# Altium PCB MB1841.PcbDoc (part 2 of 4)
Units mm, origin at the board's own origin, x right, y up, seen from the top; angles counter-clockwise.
Board outline 70 x 82.5 mm, 4 copper layers (Top Layer, Signal Layer 1, Signal Layer 2, Bottom Layer), stack 1.49 mm thick; 252 components, 169 nets, 1058 pads, 796 vias.
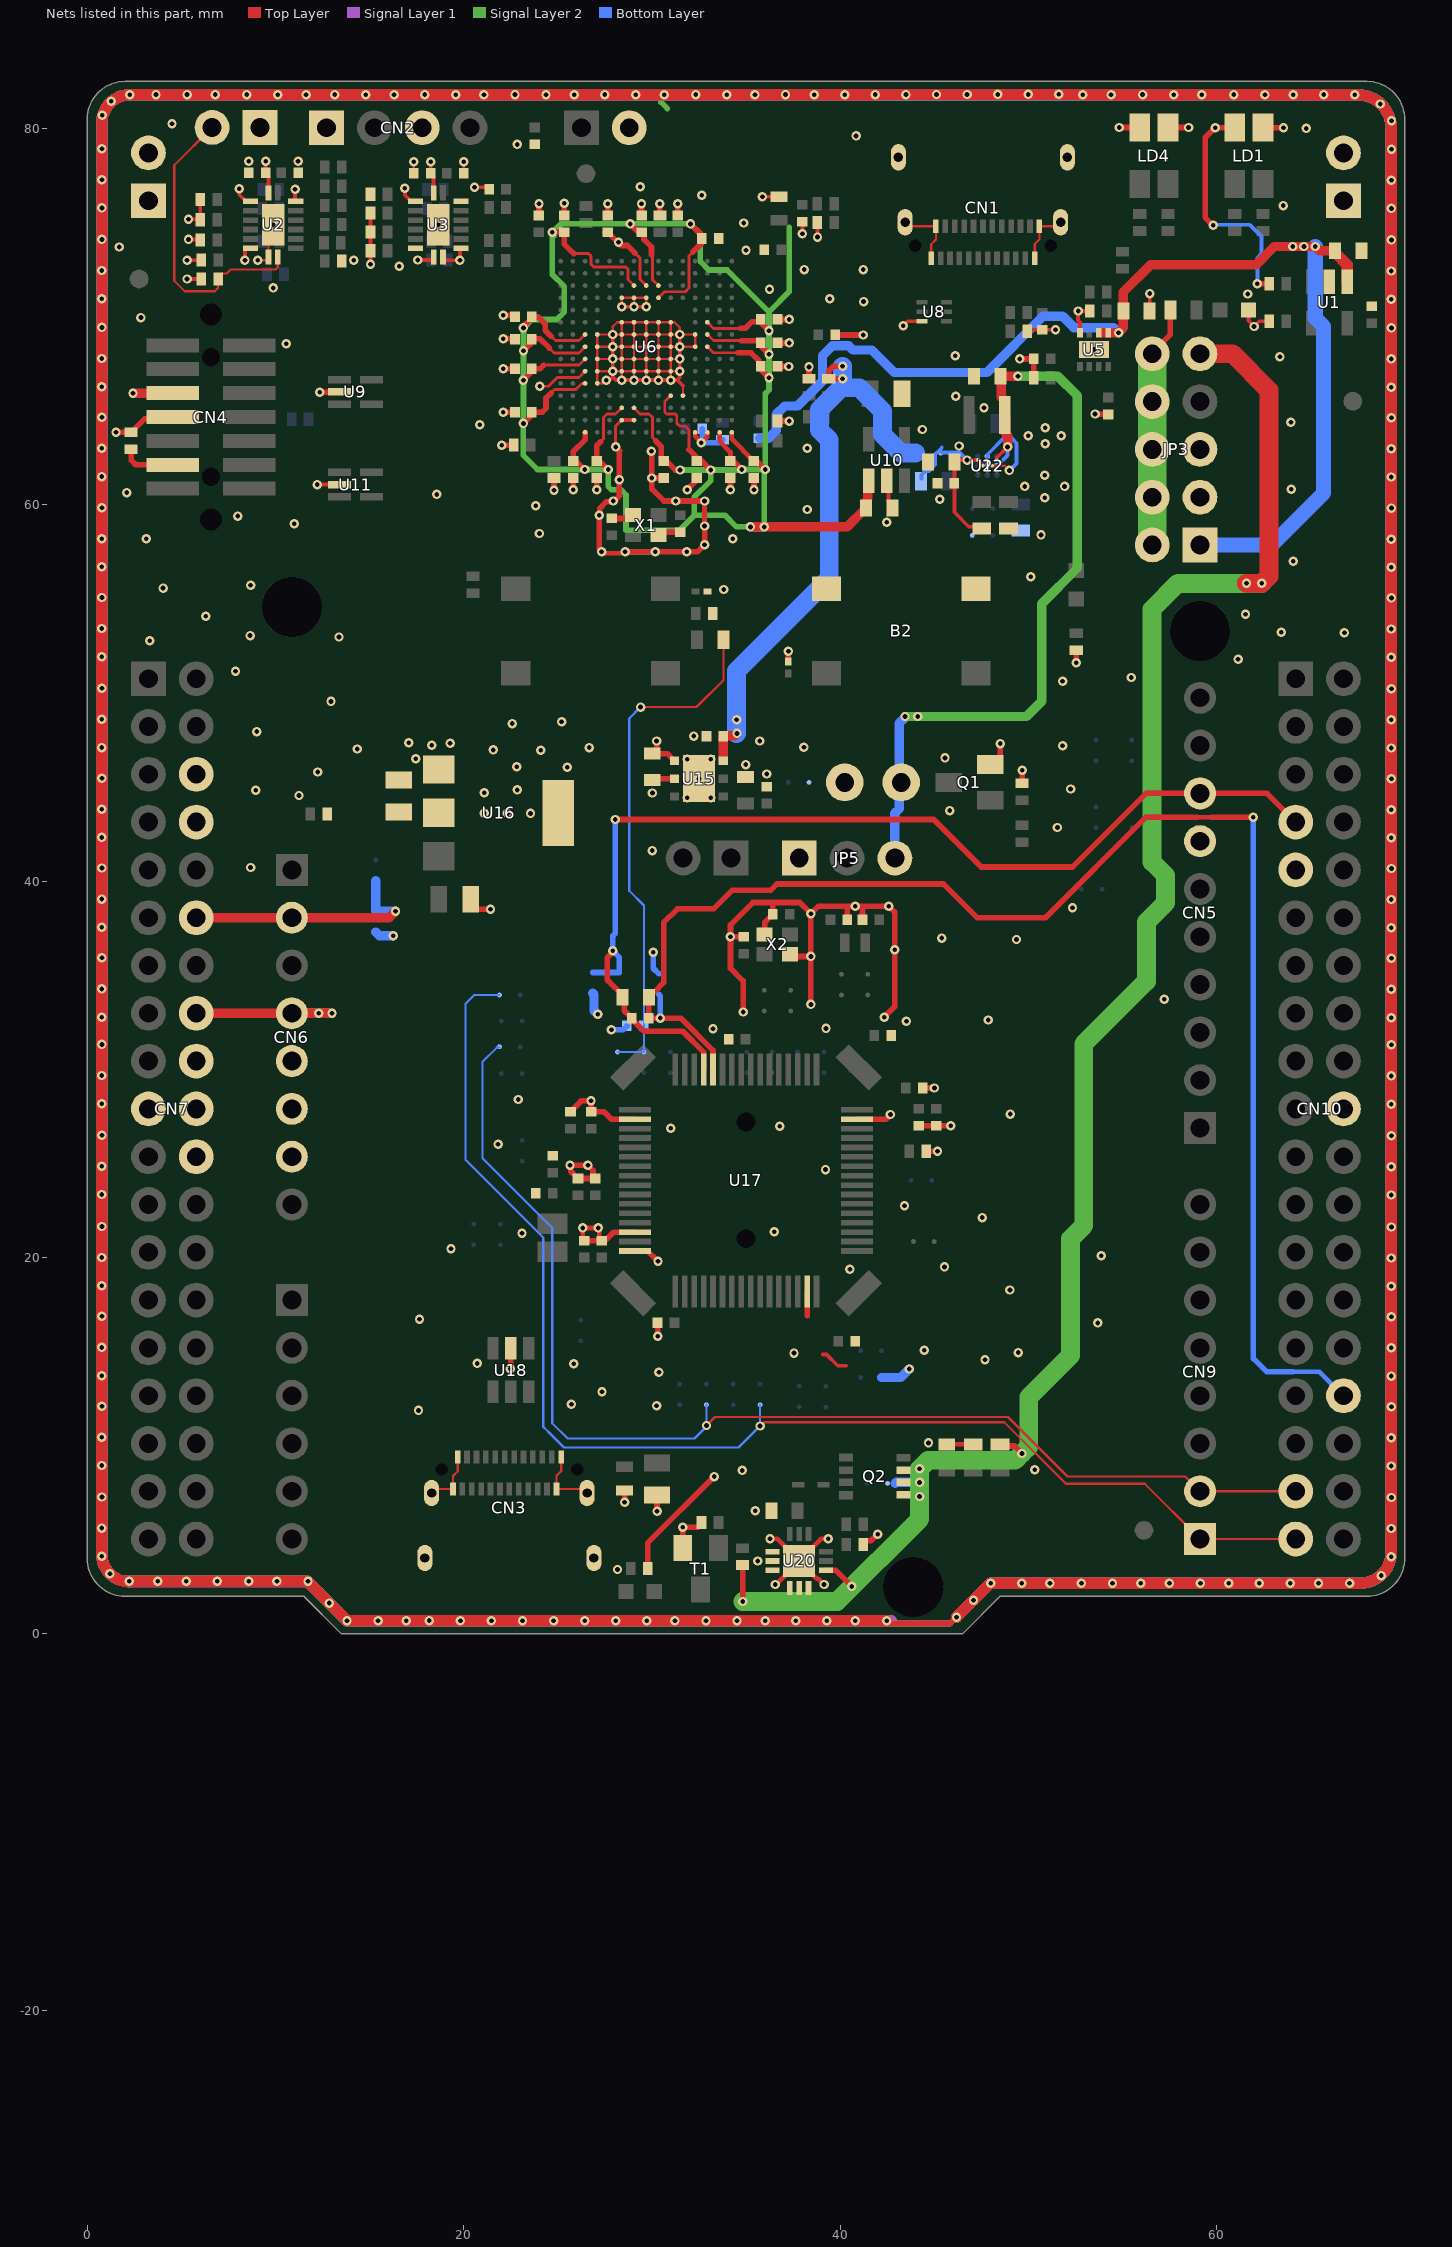
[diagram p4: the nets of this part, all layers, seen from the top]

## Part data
B1 B2: library part MCD-02524, "Push Button, SPST-NO, 0.05A, 12V SMT, T=7.30mm, changeable caps AKTSC62x", Manufacturer="APEM INC", Manufacturer_Part_Number=ADTSM644SVTR, Package=N/A
C1 C2 C3 C4 C5 C9 C10 C11 C13 C19 C20 C22 C23 C25 C26 C30 C32 C33 C34 C35 C36 C37 C38 C42 C46 C53 C54 C55 C56 C57 C60 C63 C66 C67 C68 C72: library part MCD-00006, "Capacitor, MLCC, 100nF, 16V, X7R, +/-10%, 0402, T=0.5mm", Manufacturer=YAGEO, Manufacturer_Part_Number=CC0402KRX7R7BB104, Package=0402
C6: library part MCD-00016, "Capacitor, MLCC, 20pF, 50V, NPO, +/- 5%, 0402, T=0.5mm", Manufacturer=YAGEO, Manufacturer_Part_Number=CC0402JRNPO9BN200, Package=0402
C7 C18 C24: library part MCD-02198, "Capacitor, MLCC, 10nF, 50V, X7R, +/-10%, 0402, T=0.5mm", Manufacturer=YAGEO, Manufacturer_Part_Number=CC0402KRX7R9BB103, Package=0402
C8 C12 C21: library part MCD-02606, "Capacitor, MLCC, 2.2uF, 6.3V, X5R, +/-10%, 0402, T=0.5mm", Manufacturer=YAGEO, Manufacturer_Part_Number=CC0402KRX5R5BB225, Package=0402
C14 C16 C39: library part MCD-00099, "Capacitor, MLCC, 10uF, 10V, X5R, +/-10%, 0603, T=0.8mm", Manufacturer=MURATA, Manufacturer_Part_Number=GRM188R61A106KE69D, Package=0603
C15 C64: library part MCD-00205, "Capacitor, MLCC, 100pF, 50V, NPO, +/-5%, 0402, T=0.5mm", Manufacturer=YAGEO, Manufacturer_Part_Number=CC0402JRNPO9BN101, Package=0402
C17 C29: library part MCD-02355, "Capacitor, MLCC, 100nF, 25V, X7R, +/-10%, 0402, T=0.5mm", Manufacturer=WALSIN, Manufacturer_Part_Number=0402B104K250CT, Package=0402
C27 C31: library part MCD-00243, "Capacitor, MLCC, 10uF, 6V3, X5R, +/-10%, 0603, T=0.8mm", Manufacturer=YAGEO, Manufacturer_Part_Number=CC0603KRX5R5BB106, Package=0603
C28 C70: library part MCD-02372, "Capacitor, MLCC, 2.2uF, 25V, X7R, +/-10%, 0805, T=1,25mm", Manufacturer=MURATA, Manufacturer_Part_Number=GRM21BR71E225KE11L, Package=0805
C40 C41: library part MCD-01374, "Capacitor, MLCC, 5.6pF, 50V, NPO, +/-0.1pF, 0402, T=0.5mm", Manufacturer=YAGEO, Manufacturer_Part_Number=CC0402BRNPO9BN5R6, Package=0402
C43 C44 C52: library part MCD-00010, "Capacitor, MLCC, 1uF, 16V, X5R, +/-10%, 0603, T=0.8mm", Manufacturer=YAGEO, Manufacturer_Part_Number=CC0603KRX5R7BB105, Package=0603
C45 C47: library part MCD-00014, "Capacitor, MLCC, 10uF, 25V, X5R, +/-10%, 0805, T=0.85mm", Manufacturer=YAGEO, Manufacturer_Part_Number=CC0805KRX5R8BB106, Package=0805
C48 C49 C50 C51: library part MCD-00674, "Capacitor, MLCC, 6.8pF, 50V, NPO, +/-0.25pF, 0402, T=0.5mm", Manufacturer=YAGEO, Manufacturer_Part_Number=CC0402CRNPO9BN6R8, Package=0402
C58 C65: library part MCD-01823, "Capacitor, MLCC, 2.2uF, 6V3, X5R,+/-10%, 0402, T=0.5mm", Manufacturer=MURATA, Manufacturer_Part_Number=GRM155R60J225KE95D, Package=0402
C59 C61 C62: library part MCD-01355, "Capacitor, MLCC, 10uF, 4V, X5R, +/-20%, 0402, T=0.5mm", Manufacturer=MURATA, Manufacturer_Part_Number=GRM155R60G106ME44, Package=0402
C69: library part MCD-00637, "Capacitor, MLCC, 10pF, 50V, NPO, +/-5%, 0603, T=0.8mm", Manufacturer=YAGEO, Manufacturer_Part_Number=CC0603JRNPO9BN100, Package=0603
C71: library part MCD-01099, "Capacitor, MLCC, 100nF, 50V, X7R, +/-10%, 0603, T=0.8mm", Manufacturer=YAGEO, Manufacturer_Part_Number=CC0603KRX7R9BB104, Package=0603
C73: library part MCD-00011, "Capacitor, MLCC, 10nF, 16V, X7R, +/-10%, 0402, T=0.5mm", Manufacturer=YAGEO, Manufacturer_Part_Number=CC0402KRX7R7BB103, Package=0402
CN1 CN3: library part MCD-03232, "USB_TypeC, 24 pins, RA, SMD, T=2.96mm (USB Certified 3.1)", Manufacturer="AMPHENOL ICC", Manufacturer_Part_Number=12401826E412A
CN2: library part MCD-00029, "Header, 4x1, 2.54mm, VR, TH, T=5.84mm/2.54mm", Manufacturer=SAMTEC, Manufacturer_Part_Number=TSW-104-07-G-S
CN4: library part MCD-01226, "Header, 5x2, 1.27mm, VR, SMD, T=5.97mm/3.05mm", Manufacturer=SAMTEC, Manufacturer_Part_Number=FTSH-105-01-L-DV-K
CN5: library part MCD-02625, "Socket, 10x1, 2.54mm, VR, TH, T=8.51mm/10mm", Manufacturer=SAMTEC, Manufacturer_Part_Number=SSQ-110-03-F-S
CN6 CN9: library part MCD-02624, "Socket, 8x1, 2.54mm, VR, TH, T=8.51mm/10mm", Manufacturer=SAMTEC, Manufacturer_Part_Number=SSQ-108-03-F-S
CN7 CN10: library part MCD-00213, "Header, 19x2, 2.54mm, VR, TH, T=5.84mm/10.16mm", Manufacturer=SAMTEC, Manufacturer_Part_Number=TSW-119-09-G-D
CN8: library part MCD-02623, "Socket, 6x1, 2.54mm, VR, TH, T=8.51mm/10mm", Manufacturer=SAMTEC, Manufacturer_Part_Number=SSQ-106-03-F-S
CN11 CN12: library part MCD-00214, "Header, 2x1, 2.54mm, VR, TH, T=5.84mm/10.16mm", Manufacturer=SAMTEC, Manufacturer_Part_Number=TSW-102-09-G-S
D1: library part MCD-01677, "Small signal Schottky diodes", Manufacturer=STMICROELECTRONICS, Manufacturer_HQ_COO=EU, Manufacturer_Part_Number=BAT54KFILM, Package=SOD-523
HW1: library part MCD-00547, "Sticker product 25x9 mm", Manufacturer=N/A
JP1 JP2: library part MCD-00045, "Header, 2x1, 2.54mm, VR, TH, T=5.84mm/2.54mm", Manufacturer=SAMTEC, Manufacturer_Part_Number=TSW-102-07-G-S
JP3: library part MCD-01203, "Header, 5x2, 2.54mm, VR, TH, T=5.84mm/2.54mm", Manufacturer=SAMTEC, Manufacturer_Part_Number=TSW-105-07-G-D
JP4: library part MCD-00683, "Header, 2x1, 2.54mm, VR, TH, T=5.84mm/2.54mm", Manufacturer=SAMTEC, Manufacturer_Part_Number=TSW-102-07-G-S
JP5: library part MCD-00684, "Header, 3x1, 2.54mm, VR, TH, T=5.84mm/2.54mm", Manufacturer=SAMTEC, Manufacturer_Part_Number=TSW-103-07-F-S
L1: library part MCD-00240, "Inductor, 2.2uH, +/-20%, 2.6A, 100mR, 2.5x2mm, T=1mm", Manufacturer=TDK, Manufacturer_Part_Number=VLS252010HBX-2R2M-1, Package=2.5x2mm
L2: library part MCD-01060, "Inductor, 2.2uH, +/-20%, 0.7A, 0R156, 0805, T=0.9mm", Manufacturer=MURATA, Manufacturer_Part_Number=LQM21PN2R2MGH, Package=0805
LD1 LD4: library part MCD-02631, "LED Bicolor, Green/Red, 2V, 20mA,  4-PLCC", Manufacturer="WURTH ELEKTRONIK", Manufacturer_Part_Number=150141SV73110, Package=4-PLCC
LD2 LD3 LD6: library part MCD-00588, "LED Green, 0603 SMD, Forward Voltage Typ=2V, Max=2.5V", Manufacturer="OSRAM OPTO SEMICONDUCTORS", Manufacturer_Part_Number="LG Q396-PS-35", Package="LED 0603"
Q1 T1: library part MCD-00073, "NPN Bipolar Transistor", Manufacturer="ON SEMICONDUCTOR", Manufacturer_Part_Number=BSR14, Package=SOT23
Q2: library part MCD-01810, "N-channel 30 V, 6 mΩ typ, 11 A STripFET™ H6, Power MOSFET in a PowerFLAT™ 3.3x3.3 package", Manufacturer=STMICROELECTRONICS, Manufacturer_HQ_COO=EU, Package="PowerFLAT 3.3x3.3"
R1 R2 R6 R21: library part MCD-00481, "Resistor, 47R, 0402, +/-1%, 1/16W", Manufacturer=YAGEO, Manufacturer_Part_Number=RC0402FR-0747RL, Package=0402
R3 R4 R5 R9 R15 R17 R18 R19 R20 R22 R24 R25 R26 R28 R29 R34 R35 R37 R48 R51: library part MCD-00059, "Resistor, 100K, 0402, +/-1%, 1/16W", Manufacturer=YAGEO, Manufacturer_Part_Number=RC0402FR-07100KL, Package=0402
R7 R42: library part MCD-00067, "Resistor, 100R, 0402, +/- 1%, 1/16W", Manufacturer=YAGEO, Manufacturer_Part_Number=RC0402FR-07100RL, Package=0402
R8 R40 R47 R66 R102 R103 R104 R105 R106 R107 R108 R109: library part MCD-00052, "Resistor, 0R, 0402, +/-5%, 1/16W", Manufacturer=YAGEO, Manufacturer_Part_Number=RC0402JR-070RL, Package=0402
R10 R12: library part MCD-00062, "Resistor, 330R, 0402, +/-1%, 1/16W", Manufacturer=YAGEO, Manufacturer_Part_Number=RC0402FR-07330RL, Package=0402
R11 R13: library part MCD-02665, "Resistor, 1K, 0402, +/-0.1%, 1/16W, +/-25ppm/°C", Manufacturer=YAGEO, Manufacturer_Part_Number=RT0402BRD071KL, Package=0402
R14 R27: library part MCD-00185, "Resistor, 3K, 0402, +/-1%, 1/16W", Manufacturer=YAGEO, Manufacturer_Part_Number=RC0402FR-073KL, Package=0402
R16 R36 R39: library part MCD-00333, "Resistor, 5K1, 0402, +/-1%, 1/16W", Manufacturer=YAGEO, Manufacturer_Part_Number=RC0402FR-075K1L, Package=0402
R23: library part MCD-00409, "Resistor, 1K8, 0402, +/-1%, 1/16W", Manufacturer=YAGEO, Manufacturer_Part_Number=RC0402FR-071K8L, Package=0402
R30: library part MCD-00381, "Resistor, 1K3, 0402, +/-1%, 1/16W", Manufacturer=YAGEO, Manufacturer_Part_Number=RC0402FR-071K3L, Package=0402
R31 R33: library part MCD-02455, "Resistor, 3K9, 0402, +/-1%, 1/16W, +/-100ppm/°C", Manufacturer=YAGEO, Manufacturer_Part_Number=RC0402FR-073K9L, Package=0402
R32: library part MCD-00225, "Resistor, 510R, 0603, +/-1%, 1/10W", Manufacturer=YAGEO, Manufacturer_Part_Number=RC0603FR-07510RL, Package=0603
R38 R41 R43 R44 R54 R57 R58 R65: library part MCD-00053, "Resistor, 10K, 0402, +/-1%, 1/16W", Manufacturer=YAGEO, Manufacturer_Part_Number=RC0402FR-0710KL, Package=0402
R45 R46 R50 R62 R63: library part MCD-00056, "Resistor, 0R, 0603, +/-5%, 1/10W", Manufacturer=YAGEO, Manufacturer_Part_Number=RC0603JR-070RL, Package=0603
R49 R61: library part MCD-00441, "Resistor, 270R, 0402, +/-1%, 1/16W", Manufacturer=YAGEO, Manufacturer_Part_Number=RC0402FR-07270RL, Package=0402
R52: library part MCD-00061, "Resistor, 1K, 0402, +/-1%,1/16W", Manufacturer=YAGEO, Manufacturer_Part_Number=RC0402FR-071KL, Package=0402
R53 R60: library part MCD-00063, "Resistor, 47K, 0402, +/-1%, 1/16W", Manufacturer=YAGEO, Manufacturer_Part_Number=RC0402FR-0747KL, Package=0402
R55: library part MCD-01171, "Resistor, 49K9, 0603, +/-1%, 1/10W", Manufacturer=YAGEO, Manufacturer_Part_Number=RC0603FR-0749K9L, Package=0603
R56: library part MCD-00458, "Resistor, 330K, 0603, +/-1%, 1/10W", Manufacturer=YAGEO, Manufacturer_Part_Number=RC0603FR-07330KL, Package=0603
R59: library part MCD-00433, "Resistor, 2K4, 0402, +/-1%, 1/16W", Manufacturer=YAGEO, Manufacturer_Part_Number=RC0402FR-072K4L, Package=0402
R64: library part MCD-00242, "Resistor, 19K6, 0603, +/-1%, 1/10W", Manufacturer=YAGEO, Manufacturer_Part_Number=RC0603FR-0719K6L, Package=0603
SB1 SB2 SB3 SB4 SB5 SB6 SB7 SB8 SB9 SB10 SB11 SB12 SB13 SB14 SB15 SB16 SB17 SB18 SB19 SB20 SB21 SB22 SB23 SB24 SB25 SB26 SB27 SB28 SB29 SB30 SB31 SB32 SB33 SB34 SB35 SB36 SB37 SB38 SB39 SB40 SB41 SB42 SB43 SB44 SB45: library part MCD-00071, "Solder Bridge ON", Manufacturer=YAGEO, Manufacturer_Part_Number=RC0603JR-070RL, Package=SB0603
TP1: library part MCD-00074, "Test Point 1mm", Manufacturer=N/A
TP2 TP3: library part MCD-01506, "Test Point trought hole 1mm/2mm", Manufacturer=N/A
U1: library part MCD-00159, "IC, Enhanced single channel power switches", Manufacturer=STMICROELECTRONICS, Package=SOT23-5
U2 U3: library part MCD-01945, "4-bit dual supply translating transceiver with configurable voltage translation; 3-state", Manufacturer=NEXPERIA, Manufacturer_Part_Number=74AVC4TD245BQ,115, Package=DHVQFN16
U4 U19: library part MCD-01207, "High power Transient voltage suppressor:25V/35A EOS and ESD transients protection.", Manufacturer=STMICROELECTRONICS, Manufacturer_HQ_COO=EU, Manufacturer_Part_Number=ESDA25P35-1U1M, Package=QFN1610
U5: library part MCD-02532, "IC, eFuse with Fast Overvoltage Protection 2.7V to 18V 4A 34mOhm 8-Pin WSON", Manufacturer="TEXAS INSTRUMENTS", Package=WSON8
U6: library part MCD-03851, "MCU, ARM Cortex-M7 32-bit, 512KB Flash, 276KB RAM, With Crypto", Manufacturer=STMICROELECTRONICS, Manufacturer_Part_Number=STM32F723IEK6, Package=BGA-176
U8: library part MCD-00649, "Common mode filter with ESD protection for USB 2.0 interface", Manufacturer=STMICROELECTRONICS, Manufacturer_HQ_COO=EU
U9 U11: library part MCD-00136, "Dual Transil array for ESD protection", Manufacturer=STMICROELECTRONICS, Manufacturer_HQ_COO=EU
U10: library part MCD-02514, "LDO, 3.3V, 300mA, High input voltage: 2.5V to 28V, SOT23-5L", Manufacturer=STMICROELECTRONICS, Package=SOT23-5L
U12: library part MCD-00228, "400mA Nano-Quiescent Step down converter", Manufacturer=STMICROELECTRONICS, Manufacturer_HQ_COO=EU
U13 U14: library part MCD-00170, "ESD protection 6V1", Manufacturer=STMICROELECTRONICS, Manufacturer_HQ_COO=EU, Manufacturer_Part_Number=ESDALC6V1-1U2
U15: library part MCD-00215, "Low quiescent current and low noise voltage regulators", Manufacturer=STMICROELECTRONICS, Manufacturer_HQ_COO=EU, Package="DFN6 3x3mm"
U16: library part MCD-00088, "IC REG LDO 5V 0.8A SOT223", Manufacturer=STMICROELECTRONICS, Manufacturer_HQ_COO=EU, Package=SOT-223
U17: library part MCD-03267, "MCU, Arm Cortex®-M33 32-bit MCU, 512 KB Flash memory, 274 KB SRAM, SMPS, Ultra-low-power, CRYPTO", Manufacturer=STMICROELECTRONICS, Package=LQFP64
U18: library part MCD-00163, "Very low capacitance ESD protection", Manufacturer=STMICROELECTRONICS, Manufacturer_HQ_COO=EU
U20: library part MCD-01809, "USB Type-C Port Protection for USB Power Delivery, PPS compliant", Manufacturer=STMICROELECTRONICS, Manufacturer_HQ_COO=EU, Package=QFN-12L
U22: library part MCD-00226, "UL Step down regulator: Opt0", Manufacturer="ANALOG DEVICES", Manufacturer_Part_Number=ADP5301ACBZ-2-R7
X1: library part MCD-01036, "Crystal, 24MHz, 6pF, +/-20ppm, 80R, 2x1.6mm", Manufacturer=NDK, Manufacturer_Part_Number=NX2016SA-24MHZ-EXS00A-CS10820, Package=2x1.6mm
X2: library part MCD-01476, "Crystal, 16 MHz, 8pF, +/-20ppm, 200R, 2x1.6mm", Manufacturer=NDK, Manufacturer_Part_Number=NX2016SA-16MHZ-EXS00A-CS07826, Package=2x1.6mm
X3: library part MCD-02291, "Crystal, 32.768kHz, 9pF, +/-20ppm, 70KR, 1.6x1mm", Manufacturer=NDK, Manufacturer_Part_Number=NX1610SE-32.768KHZ-EXS00A-MU01499, Package=1.6x1mm

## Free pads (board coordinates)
  round 3.2 hole 3.2 unplated: 0(10.87,54.57) 0(43.89,2.5) 0(59.13,53.3)
  round 3.2 on Mech2: 0(10.87,54.57) 0(43.89,2.5) 0(59.13,53.3)
  round 0.508 on Mech16: 1(11.398,-28.906) 1(60.246,-28.906)

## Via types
v1: diameter 0.5, hole 0.25, Top Layer to Bottom Layer, tented both sides, 796 vias

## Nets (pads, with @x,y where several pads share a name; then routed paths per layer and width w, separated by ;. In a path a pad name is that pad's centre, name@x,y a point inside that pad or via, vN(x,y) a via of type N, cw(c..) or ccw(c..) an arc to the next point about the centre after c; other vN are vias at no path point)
1V8: C27.2 JP5.3 L1.2 TP2.1 U12.E3 U22.C2 | length 43.8
  Top Layer w0.2: U12.E3@48.325,62.387 48.325,62.5 v1(48.9,63.075)
  Top Layer w0.5: C27.2@48.595,67.02 48.525,66.95 C27.2@48.525,66.837 ; L1.2@48.7,64.825 48.7,65.6 48.575,65.725 48.575,66.775 C27.2@48.525,66.825 C27.2@48.525,66.837 ; L1.2@48.75,64.775 48.8,64.725 48.8,63.775 48.9,63.675 v1(48.9,63.075) ; v1(49.45,66.825) 49.45,66.837 C27.2@48.525,66.837
  Signal Layer 2 w0.5: v1(43.45,48.75) v1(44.125,48.75) 49.902,48.75 50.725,49.573 50.725,54.75 52.6,56.625 52.6,65.8 51.575,66.825 v1(49.45,66.825)
  Bottom Layer w0.2: U22.C2@48.325,62.075 48.348,62.075 48.9,62.627 v1(48.9,63.075)
  Bottom Layer w0.5: JP5.3@42.915,41.225 42.915,43.615 43.15,43.85 43.15,48.4 43.45,48.7 v1(43.45,48.75) v1(44.125,48.75)
3V3: CN6.4 CN7.16 JP5.1 R49.2 R61.2 SB8.2 SB11.1 SB14.1 SB33.1 TP3.1 | length 20.3
  Top Layer w0.3: R61.2@29.775,3.475 29.775,4.825 v1(33.312,8.362) ; v1(52.55,51.6) R49.2@52.55,52.275
  Top Layer w0.5: CN7.16@5.79,32.98 5.795,32.975 v1(12.3,32.975) v1(13,32.975)
  Signal Layer 2 w0.5: CN6.4@10.87,32.98 12.995,32.98 v1(13,32.975)
  Bottom Layer w0.5: SB11.1@15.325,37.3 15.525,37.1 v1(16.25,37.1) ; SB14.1@26.85,34.05 26.925,33.975 26.925,33.125 v1(27.125,32.925) ; SB33.1@42.2,13.625 43.225,13.625 v1(43.675,14.075)
3V3_STLK: C2.2 C4.2 C9.1 C10.1 C11.1 C13.1 C19.1 C20.1 C22.1 C23.1 C25.1 C26.1 C30.1 C32.1 C33.1 C34.1 C35.1 C36.1 C37.1 C39.2 CN2.1 JP1.1 LD1.4 LD4.4 R4.2 R9.2 R15.2 R18.2 R19.1 R22.2 R24.1 R29.2 R44.2 R65.2 U2.1 U2.2 U2.7 U2.15 U3.1 U3.2 U6.C1 U6.C5 U6.C6 U6.C7 U6.C8 U6.C9 U6.F3 U6.G3 U6.G13 U6.H13 U6.J12 U6.J13 U6.K4 U6.N8 U6.N9 U6.N10 U6.P1 U6.R1 U10.1 | length 180.7
  Top Layer w0.12: R19.1@5.975,74.1 R19.1@6,74.075
  Top Layer w0.15: v1(24.046,66.293) 24.052,66.3 24.5,66.3 24.97,66.77 26.12,66.77 U6.C6@26.45,67.1 ; 24.255,67.42 24.265,67.43 26.13,67.43 U6.C7@26.45,67.75 ; 24.55,68.325 24.805,68.07 26.12,68.07 U6.C8@26.45,68.4 ; 24.65,65.95 24.825,66.125 25.955,66.125 26.28,66.45 U6.C5@26.45,66.45 ; 24.65,68.95 24.875,68.725 26.125,68.725 U6.C9@26.45,69.05 ; 27.275,63.35 27.43,63.505 27.43,64.633 27.617,64.82 28.07,64.82 U6.F3@28.4,65.15 ; U6.G3@29.05,65.15 29.37,64.83 29.845,64.83 30.025,64.65 30.025,63.575 30.2,63.4 ; U6.J12@30.35,71 30.67,71.32 31.773,71.32 31.98,71.527 31.98,73.23 32.175,73.425 ; U6.K4@31,65.8 30.68,65.48 30.68,64.926 30.785,64.821 31.242,64.821 31.325,64.738 31.325,64.336 31.491,64.17 31.783,64.17 31.975,63.978 31.975,62.934 ; U6.N8@32.95,68.4 33.27,68.08 34.58,68.08 ; U6.N9@32.95,69.05 33.275,68.725 34.75,68.725 ; U6.N10@32.95,69.7 33.275,69.375 34.725,69.375
  Top Layer w0.16: 25.84,73.35 26.625,73.35 26.775,73.2 26.775,73.085 26.775,72.775 26.925,72.625 28.5,72.625 ; 28.535,72.625 28.625,72.625 28.725,72.525 28.725,72.165 28.725,71.975 U6.G13@29.05,71.65 ; 29.1,73.375 29.375,73.1 29.375,71.975 U6.H13@29.7,71.65 ; 29.98,73.3 30.025,73.255 30.025,71.975 U6.J13@30.35,71.65
  Top Layer w0.2: v1(5.3,73) R24.1@6.05,73 ; v1(5.375,74.1) R19.1@5.975,74.1 ; v1(5.375,75.175) 5.975,75.175 R15.2@6,75.15 ; R15.2@5.925,75.2 6,75.275 R4.2@6,76.225 ; v1(8.075,76.8) 8.075,76.475 8.335,76.215 8.425,76.125 U2.2@8.675,76.125 ; v1(8.375,73) 8.375,73.535 8.465,73.625 U2.7@8.675,73.625 ; v1(9.475,78.25) C2.2@9.475,77.65 9.625,77.5 U2.1@9.625,76.575 ; v1(11.04,76.775) 11.04,76.16 U2.15@11.075,76.125 ; v1(15.05,72.775) R22.2@15.05,73.5 R18.2@15.05,74.5 R9.2@15.05,75.5 ; v1(16.875,76.825) 16.875,76.45 17.11,76.215 17.2,76.125 U3.2@17.45,76.125 ; v1(18.25,78.225) C4.2@18.25,77.625 18.4,77.475 U3.1@18.4,76.575
  Top Layer w0.25: U6.P1@33.6,63.85 33.6,63.375 34.175,62.8 C36.1@34.175,62.325 ; U6.R1@34.25,63.85 34.25,63.5 C37.1@35.425,62.325
  Top Layer w0.3: v1(22.018,63.17) R65.2@22.668,63.17 ; v1(23.175,64.325) 23.625,64.775 C30.1@23.625,64.925 24.175,64.925 24.375,65.125 24.375,65.675 24.65,65.95 ; v1(23.175,66.625) 23.625,67.075 C26.1@23.625,67.225 24.05,67.225 24.245,67.42 24.255,67.42 ; v1(23.175,69.4) 23.213,69.438 23.213,69.513 23.52,69.82 23.52,69.895 C19.1@23.625,70 ; v1(23.18,68.18) 23.52,68.52 23.52,68.72 23.625,68.825 24.05,68.825 24.55,68.325 ; C19.1@23.73,70 23.948,70 24.325,69.623 24.325,69.275 24.65,68.95 ; v1(24.7,74.475) C9.1@25.35,74.475 25.35,73.84 25.84,73.35 ; v1(24.8,60.775) R44.2@24.8,61.425 ; v1(26.425,61.875) 25.975,62.325 C32.1@25.825,62.325 25.825,62.825 26.45,63.45 U6.C1@26.45,63.85 ; 27.275,63.35 27.075,63.15 C33.1@27.075,62.325 27.225,62.325 v1(27.675,61.875) ; C10.1@27.5,74.475 C10.1@27.65,74.475 ; C10.1@27.65,74.45 27.7,74.45 28.375,73.775 28.7,73.775 29.1,73.375 ; v1(28.85,74.925) 29.3,74.475 C11.1@29.45,74.475 29.475,74.475 29.58,74.37 29.58,74.095 29.98,73.695 29.98,73.3 ; 30.2,63.4 30.5,63.1 30.5,62.45 C34.1@30.625,62.325 30.775,62.325 31.251,61.849 v1(31.499,61.849) ; 31.975,62.934 32.375,62.534 C35.1@32.375,62.325 32.647,62.325 v1(33.123,61.849) ; v1(32.05,74.925) 32.65,74.325 C13.1@32.65,74.15 32.65,73.9 32.175,73.425 ; C36.1@34.175,62.325 34.325,62.325 v1(34.775,61.875) ; 34.58,68.08 34.575,68.075 35.275,68.075 35.67,67.68 35.67,67.455 C25.1@35.775,67.35 35.775,67.2 v1(36.225,66.75) ; 34.725,69.375 34.96,69.375 35.319,69.734 35.67,69.734 C20.1@35.775,69.839 ; 34.75,68.725 35.67,68.725 35.675,68.72 35.675,68.7 C23.1@35.775,68.6 ; C37.1@35.425,62.325 35.575,62.325 v1(36.025,61.875) ; C23.1@35.775,68.45 v1(36.225,68) ; C20.1@35.775,69.85 C20.1@35.775,69.839 ; v1(36.225,69.25) 35.775,69.7 C20.1@35.775,69.839 ; v1(54.83,80.05) LD4.4@55.925,80.05 ; v1(59.825,74.85) 59.4,75.275 59.4,79.505 v1(59.935,80.04) ; v1@59.94,80.04 LD1.4@60.995,80.04 ; v1(62.175,71.75) R29.2@62.8,71.75
  Top Layer w0.5: v1(35.238,58.825) v1(35.975,58.825) 40.375,58.825 41.31,59.76 41.31,59.905 41.33,59.905 41.445,60.02 41.445,60.281 41.476,60.313 41.476,60.876 U10.1@41.575,60.975
  Signal Layer 2 w0.3: v1(24.7,74.475) 24.7,72.25 25.35,71.6 25.35,70.25 24.943,69.843 23.632,69.843 23.189,69.4 v1(23.175,69.4) 23.177,69.398 23.177,68.177 23.175,68.175 23.177,68.173 23.177,66.627 v1(23.175,66.625) v1(23.175,64.325) 23.171,64.321 23.171,62.629 23.925,61.875 v1(26.425,61.875) v1(27.675,61.875) 27.675,60.981 27.851,60.805 28.345,60.805 28.625,60.525 28.625,58.65 31.475,58.65 32.275,59.45 ; v1@24.725,74.5 25.15,74.925 25.25,74.925 ; v1@24.82,74.301 24.723,74.398 25.25,74.925 ; v1(31.499,61.849) v1(33.123,61.849) ; 37.3,74.75 37.3,71.325 36.225,70.25 ; 25.25,74.925 v1(28.85,74.925) v1(32.05,74.925) 32.575,74.4 32.575,72.925 33.025,72.475 34,72.475 36.225,70.25 ; 32.275,59.45 32.255,59.47 32.255,60.405 33.123,61.273 v1(33.123,61.849) ; 32.275,59.45 33.875,59.45 34.5,58.825 v1(35.238,58.825) v1(35.975,58.825) 35.975,61.825 v1(36.025,61.875) ; v1(33.123,61.849) 34.749,61.849 v1(34.775,61.875) v1(36.025,61.875) ; v1(36.025,61.875) 36.025,65.9 36.225,66.1 v1(36.225,66.75) v1(36.225,68) v1(36.225,69.25) 36.225,70.25
  Bottom Layer w0.2: v1(59.825,74.85) 59.85,74.875 61.775,74.875 62.4,74.25 62.4,73.35 62.175,73.125 v1(62.175,71.75)
  Bottom Layer w0.5: v1(35.238,58.825) v1(35.975,58.825)
  other v1: 28.225,73.95
5V: C42.2 C43.2 CN6.5 CN7.18 JP3.2 JP3.4 JP3.6 JP3.8 JP3.10 R32.2 R39.2 SB5.1 U15.1 U15.6 | length 47.2
  Top Layer w0.3: C43.2@30.025,46.775 C43.2@30.08,46.775 ; v1(30.25,47.45) 30.25,46.945 C43.2@30.08,46.775 ; U15.1@31.2,46.4 31.175,46.4 31.1,46.475 31.1,46.5 30.825,46.775 C43.2@30.08,46.775 ; v1(40.132,66.693) 39.407,66.693 R39.2@39.4,66.7 39.4,67.111 39.649,67.361 v1(40.132,67.361) ; JP3.10@56.585,68.085 57.55,69.05 R32.2@57.55,70.35
  Top Layer w0.5: U15.6@33.8,46.475 C42.2@33.8,47.7 33.8,47.725 33.805,47.73 34.405,47.73 v1(34.525,47.85)
  Signal Layer 2 w1.5: JP3.2@56.585,57.865 JP3.4@56.585,60.405 JP3.6@56.585,62.945 JP3.8@56.585,65.485 JP3.10@56.585,68.025
  Bottom Layer w1: v1@34.5,47.85 v1(34.5,48.575) 34.5,51.175 39.425,56.1 39.425,63.45 38.9,63.975 38.9,65.062 40.157,66.319 40.132,66.345 v1(40.132,66.693) v1(40.132,67.361) ; 40.157,66.218 41.021,66.218 42.25,64.989 42.25,63.75 43.25,62.75 44,62.75
5V_SMPS_IN: C31.2 C38.2 R45.2 R63.1 SB5.2 U12.A3 U12.B2 | length 10.1
  Top Layer w0.2: R45.2@47.525,58.75 47.442,58.833 46.842,58.833 46.075,59.6 C38.2@46.075,61.15 C31.2@46.075,62.275 46.175,62.375 v1(46.75,62.375) 46.762,62.387 U12.A3@47.325,62.387 47.575,62.137 U12.B2@47.575,62.075
  Bottom Layer w0.2: R63.1@44.325,61.4 44.325,61.58 44.545,61.8 44.725,61.8 45.05,62.125 45.05,62.675 45.275,62.9 ; 45.4,63.05 45.4,63.035 45.373,63.008 45.373,62.998 45.275,62.9 ; v1(46.75,62.375) 46.35,62.775 45.4,62.775 45.275,62.9
  other v1: 46.325,63.125
5V_STLK: C14.2 C16.2 JP3.1 R27.1 U1.1 U5.5 U5.6 | length 64.1
  Top Layer w0.5: U5.6@53.85,69.15 v1(54.8,69.15) 55.05,69.4 C16.2@55.05,70.225 ; C16.2@55.075,70.275 C16.2@55.05,70.3 55.05,71.3 56.5,72.75 62.1,72.75 63.075,73.725 v1(64.05,73.725) v1(64.65,73.725) v1(65.25,73.725) 65.475,73.5 C14.2@66.275,73.5
  Top Layer w0.6: C14.2@66.3,73.4 66.3,73.375 66.32,73.355 66.345,73.355 66.95,72.75 U1.1@66.95,71.85
  Signal Layer 2 w0.5: v1(64.05,73.725) v1(65.25,73.725)
  Bottom Layer w0.5: R27.1@35.738,63.533 36.202,63.533 36.601,63.932 36.601,64.795 37.056,65.25 37.742,65.25 39.065,66.573 39.065,67.92 39.599,68.453 40.462,68.453 40.691,68.224 41.681,68.224 42.875,67.031 47.803,67.031 50.8,70.028 51.816,70.028 52.426,69.418 54.532,69.418 v1(54.8,69.15)
  Bottom Layer w0.8: JP3.1@59.125,57.865 62.94,57.865 65.7,60.625 65.7,69.475 65.25,69.925 v1(65.25,73.725)
5V_UCPD: JP3.9 Q2.1 Q2.2 Q2.3 R56.2 R60.1 SB40.1 U20.4 | length 96.4
  Top Layer w0.3: R60.1@34.813,3.663 34.825,3.65 v1(34.825,1.725) ; U20.4@39.25,3.375 39.775,3.375 v1(40.625,2.525) ; R56.2@48.5,10.075 48.591,9.984 49.266,9.984 v1(49.663,9.588)
  Top Layer w1: JP3.9@59.125,68.025 60.855,68.025 62.789,66.091 62.789,56.206 62.412,55.829 v1(61.595,55.829)
  Signal Layer 2 w1: v1(34.825,1.725) 39.85,1.725 44.225,6.1 v1(44.225,7.3) v1(44.225,8.05) v1(44.225,8.775) 44.675,9.225 49.3,9.225 v1(49.663,9.588) 50.025,9.95 50.025,12.575 52.25,14.8 52.25,21 52.95,21.7 52.95,31.35 56.275,34.675 56.275,37.825 57.3,38.85 57.3,40.3 56.575,41.025 56.575,54.45 57.95,55.825 v1(62.408,55.825)
  Bottom Layer w0.5: 42.925,8 42.975,8.05 v1(44.225,8.05)
5V_VIN: C45.2 JP3.3 R52.1 U16.2 U16.4
  other v1: 22.325,43.6 23.55,43.6 21.1,43.615 21.1,44.7 22.85,44.85 25.5,46.05 22.825,46.075 24.1,46.95 21.575,46.975 26.675,47.1 50.875,60.375 49.82,60.975 51.93,60.975 50.875,61.575
AGND: C52.2 C53.1 CN10.32 SB12.2 U17.12 | length 81.4
  Top Layer w0.25: 58.971,43.389 59.739,43.389
  Top Layer w0.3: U17.12@33.25,30 33.25,31.009 31.544,32.715 C53.1@29.835,32.715 29.835,33.82 C52.2@29.84,33.825 29.84,33.95 30.01,34.12 30.135,34.12 30.625,34.61 30.625,37.8 31.355,38.53 33.28,38.53 34.275,39.525 36.325,39.525 36.65,39.85 45.5,39.85 47.3,38.05 50.9,38.05 56.239,43.389 58.971,43.389 ; 59.739,43.389 v1(61.961,43.389)
  Bottom Layer w0.25: 64.051,13.935 65.475,13.935 CN10.32@66.75,12.66
  Bottom Layer w0.3: SB12.2@30.375,33.975 30.45,33.9 v1(30.45,32.725) ; v1(61.961,43.389) 61.961,14.639 62.665,13.935 64.051,13.935
ARD_D0_RX: CN9.1 CN10.37 SB15.2 SB34.1 | length 70.9
  Top Layer w0.12: v1(35.75,11.05) 35.788,11.05 35.988,11.25 48.725,11.25 52,7.975 56.195,7.975 CN9.1@59.13,5.04 CN10.37@64.21,5.04
  Bottom Layer w0.12: SB15.2@21.9,33.95 20.566,33.95 20.1,33.484 20.1,25.2 24.23,21.07 24.23,11.002 24.275,10.957 24.641,10.591 25.327,9.905 34.605,9.905 v1(35.75,11.05) SB34.1@35.75,12.175
ARD_D1_TX: CN9.2 CN10.35 SB17.2 SB36.1 | length 65
  Top Layer w0.12: v1(32.9,11.075) 33.35,11.525 48.925,11.525 52.085,8.365 58.345,8.365 CN9.2@59.13,7.58 CN10.35@64.21,7.58
  Bottom Layer w0.12: SB17.2@21.884,31.164 21.874,31.174 21.78,31.174 21.758,31.153 21.753,31.153 21,30.4 21,25.275 24.71,21.565 24.71,11.201 25.526,10.385 32.26,10.385 32.9,11.025 v1(32.9,11.075) SB36.1@32.9,12.175
AVDD: C52.1 C53.2 CN5.8 CN10.7 SB13.2 SB14.2 U17.13 | length 58.8
  Top Layer w0.3: v1(27.925,36.3) 27.925,36.246 27.625,35.946 27.625,34.765 27.845,34.545 27.845,34.528 28.003,34.37 28.02,34.37 28.44,33.95 C52.1@28.44,33.825 28.533,33.732 28.533,33.117 28.805,32.845 28.83,32.845 28.935,32.74 C53.2@28.935,32.715 ; v1(28.05,43.275) 44.975,43.275 47.5,40.75 52.35,40.75 56.264,44.664 CN5.8@59.13,44.664 62.686,44.664 CN10.7@64.21,43.14 ; C53.2@29.04,32.568 29.583,32.025 31.64,32.025 32.75,30.915 U17.13@32.75,30
  Bottom Layer w0.3: SB14.2@26.85,35.15 SB13.2@28.275,35.15 28.275,35.95 v1(27.925,36.3) 27.925,37.1 28.05,37.225 v1(28.05,43.275)
B_USER: C72.2 R50.2 SB23.1 SB24.1 | length 27.4
  Top Layer w0.12: v1(29.4,49.25) 32.375,49.25 33.8,50.675 R50.2@33.8,52.825
  Bottom Layer w0.12: SB24.1@28.175,30.925 SB23.1@29.575,30.925 C72.2@29.575,32.315 29.575,38.711 28.8,39.486 28.8,48.65 v1(29.4,49.25)
E5V: CN7.6 JP3.5
  other v1: 50.9,63.25 50,63.675 51.75,63.675 50.9,64.1
GND: B2.3 B2.4 C1.1 C2.1 C3.2 C4.1 C5.1 C6.2 C7.2 C8.1 C9.2 C10.2 C11.2 C12.1 C13.2 C14.1 C15.2 C16.1 C17.1 C18.2 C19.2 C20.2 C21.1 C22.2 C23.2 C24.1 C25.2 C26.2 C27.1 C28.1 C29.1 C30.2 C31.1 C32.2 C33.2 C34.2 C35.2 C36.2 C37.2 C38.1 C39.1 C40.2 C41.2 C42.1 C43.1 C44.1 C45.1 C46.1 C47.1 C48.1 C49.1 C50.1 C51.1 C54.1 C55.1 C56.1 C57.1 C58.1 C59.1 C60.1 C61.1 C62.1 C63.1 C64.1 C65.1 C66.1 C67.1 C68.1 C69.1 C70.1 C71.1 C72.1 C73.2 CN1.A1 CN1.A12 CN1.B1 CN1.B12 CN1.SH1 CN1.SH2 CN1.SH3 CN1.SH4 CN2.3 CN3.A1 CN3.A12 CN3.B1 CN3.B12 CN3.SH1 CN3.SH2 CN3.SH3 CN3.SH4 CN4.5 CN4.7 CN5.7 CN6.6 CN6.7 CN7.8 CN7.19 CN7.20 CN7.22 CN10.9 CN10.20 CN11.1 CN11.2 CN12.1 CN12.2 JP2.2 LD1.3 LD3.2 LD4.3 Q1.2 R3.1 R14.2 R16.2 R26.1 R28.1 R31.2 R33.2 R35.1 R36.2 R37.1 R38.2 R41.2 R42.1 R46.2 R48.1 R51.1 R54.1 R55.1 R57.1 R59.2 R64.2 SB7.1 SB12.1 T1.2 U1.2 U2.8 U2.17 U3.7 U3.8 U3.9 U3.10 U3.15 U3.17 U4.2 U5.8 U5.9 U6.D5 U6.D6 U6.D7 U6.D8 U6.D9 U6.F2 U6.F6 U6.F7 U6.F8 U6.F9 U6.F10 U6.F12 U6.G2 U6.G6 U6.G7 U6.G8 U6.G9 U6.G10 U6.G12 U6.H6 U6.H7 U6.H8 U6.H9 U6.H10 U6.H12 U6.J6 U6.J7 U6.J8 U6.J9 U6.J10 U6.K6 U6.K7 U6.K8 U6.K9 U6.K10 U6.L4 U6.M1 U6.M8 U6.M9 U6.N1 U8.3 U9.2 U10.2 U11.2 U12.D2 U13.2 U14.2 U15.2 U15.EP U16.1 U17.18 U17.30 U17.32 U17.47 U17.63 U18.2 U19.2 U20.1 U20.2 U20.3 U20.10 U20.11 U20.12 U20.13 U22.B1 U22.B2 X1.2 X1.4 X2.2 X2.4 | length 1431
  Top Layer w0.12: v1(9.05,73) 9.535,73 9.625,73.09 U2.8@9.625,73.175 U2.17@9.625,74.455 ; C4.1@17.35,77.625 v1(17.35,78.225) ; CN3.SH1@18.298,7.486 18.508,7.696 CN3.B12@19.428,7.696 19.428,8.389 19.678,8.639 CN3.A1@19.678,9.396 ; C5.1@20,77.625 v1(20,78.225) ; CN3.A12@25.178,9.396 25.178,8.652 24.928,8.402 CN3.B1@24.928,7.696 26.348,7.696 CN3.SH2@26.558,7.486 ; U6.D5@27.1,66.45 U6.D6@27.1,67.1 ; U6.D5@27.106,66.456 27.366,66.456 ; v1(28.4,66.625) U6.F6@28.4,67.1 ; v1(28.4,70.525) U6.F12@28.4,71 U6.G12@29.05,71 ; v1(29.05,66.625) U6.G6@29.05,67.1 ; v1(29.05,70.525) U6.G12@29.05,71 ; v1(29.7,66.625) U6.H6@29.7,67.1 ; v1(29.7,70.525) U6.H12@29.7,71 U6.G12@29.05,71 ; v1(30.35,66.625) U6.J6@30.35,67.1 ; v1(31,66.625) U6.K6@31,67.1 ; v1@31.275,60.15 v1(31.275,60.2) ; v1(31.475,67.1) U6.K6@31,67.1 ; v1(31.475,67.75) U6.K7@31,67.75 ; U6.L4@31.65,65.8 31.65,66.325 ; CN1.SH2@43.462,75.013 43.672,74.803 CN1.B1@45.092,74.803 45.092,74.097 44.842,73.847 CN1.A12@44.842,73.103 ; CN1.A1@50.342,73.103 50.342,73.861 50.592,74.111 CN1.B12@50.592,74.803 CN1.SH1@51.512,74.803 ; U2.17@9.625,74.455 9.875,74.705 v1(9.875,74.875) 9.625,74.625 U2.17@9.625,74.455 ; U6.D6@27.1,67.1 v1(27.925,67.1) U6.F6@28.4,67.1 ; U6.D6@27.1,67.1 U6.D7@27.1,67.75 ; U6.D7@27.1,67.75 v1(27.925,67.75) U6.F7@28.4,67.75 ; U6.D7@27.1,67.75 U6.D8@27.1,68.4 ; U6.D8@27.1,68.4 v1(27.925,68.4) U6.F8@28.4,68.4 ; U6.D8@27.1,68.4 U6.D9@27.1,69.05 v1(27.925,69.05) ; v1(27.925,69.05) U6.F9@28.4,69.05 ; v1(27.925,69.05) 27.925,69.471 28.154,69.7 U6.F10@28.4,69.7 ; U6.F6@28.4,67.1 U6.G6@29.05,67.1 ; U6.F6@28.4,67.1 U6.F7@28.4,67.75 ; U6.F7@28.4,67.75 U6.F8@28.4,68.4 ; U6.F7@28.4,67.75 U6.G7@29.05,67.75 ; U6.F8@28.4,68.4 U6.F9@28.4,69.05 ; U6.F8@28.4,68.4 U6.G8@29.05,68.4 ; U6.F9@28.4,69.05 U6.F10@28.4,69.7 ; U6.F9@28.4,69.05 U6.G9@29.05,69.05 ; U6.F10@28.4,69.7 U6.G10@29.05,69.7 ; U6.G6@29.05,67.1 U6.H6@29.7,67.1 ; U6.G6@29.05,67.1 U6.G7@29.05,67.75 ; U6.G7@29.05,67.75 U6.G8@29.05,68.4 ; U6.G7@29.05,67.75 U6.H7@29.7,67.75 ; U6.G8@29.05,68.4 U6.G9@29.05,69.05 ; U6.G8@29.05,68.4 U6.H8@29.7,68.4 ; U6.G9@29.05,69.05 U6.G10@29.05,69.7 ; U6.G9@29.05,69.05 U6.H9@29.7,69.05 ; U6.G10@29.05,69.7 U6.H10@29.7,69.7 ; U6.H6@29.7,67.1 U6.J6@30.35,67.1 ; U6.H6@29.7,67.1 U6.H7@29.7,67.75 ; U6.H7@29.7,67.75 U6.H8@29.7,68.4 ; U6.H7@29.7,67.75 U6.J7@30.35,67.75 ; U6.H8@29.7,68.4 U6.H9@29.7,69.05 ; U6.H8@29.7,68.4 U6.J8@30.35,68.4 ; U6.H9@29.7,69.05 U6.H10@29.7,69.7 ; U6.H9@29.7,69.05 U6.J9@30.35,69.05 ; U6.H10@29.7,69.7 U6.J10@30.35,69.7 ; U6.J6@30.35,67.1 U6.J7@30.35,67.75 ; U6.J6@30.35,67.1 U6.K6@31,67.1 ; U6.J7@30.35,67.75 U6.J8@30.35,68.4 ; U6.J7@30.35,67.75 U6.K7@31,67.75 ; U6.J8@30.35,68.4 U6.J9@30.35,69.05 ; U6.J8@30.35,68.4 U6.K8@31,68.4 ; U6.J9@30.35,69.05 U6.J10@30.35,69.7 ; U6.J9@30.35,69.05 U6.K9@31,69.05 ; U6.J10@30.35,69.7 U6.K10@31,69.7 ; U6.K6@31,67.1 U6.K7@31,67.75 ; U6.K7@31,67.75 U6.K8@31,68.4 ; U6.K8@31,68.4 U6.K9@31,69.05 ; U6.K8@31,68.4 v1(31.475,68.4) U6.M8@32.3,68.4 U6.M9@32.3,69.05 v1(31.475,69.05) ; U6.K9@31,69.05 U6.K10@31,69.7 ; U6.K9@31,69.05 v1(31.475,69.05) ; U6.K10@31,69.7 31.2,69.7 31.475,69.425 v1(31.475,69.05)
  Top Layer w0.15: v1(28.075,63.075) 28.075,64.175 U6.F2@28.4,64.5 ; U12.D2@48.075,62.075 48.745,62.075
  Top Layer w0.2: v1(5.3,72) R28.1@6.05,72 ; v1(12.225,61.075) U11.2@13.4,61.075 ; v1(17.56,73.01) 18.35,73.01 18.4,73.06 U3.8@18.4,73.175 ; U3.9@18.9,73.175 18.9,73.05 18.95,73 v1(19.8,73) 19.8,73.575 U3.10@19.85,73.625 ; v1(20.575,76.875) 21.25,76.875 C6.2@21.35,76.775 ; U6.D5@27.1,66.45 U6.D5@27.106,66.456 ; 27.366,66.456 27.535,66.625 v1(27.575,66.625) ; v1@27.656,66.625 v1(27.575,66.625) ; v1(27.925,69.05) v1(27.925,68.4) v1(27.925,67.75) v1(27.925,67.1) 27.925,66.8 ; U6.F2@28.4,64.5 U6.G2@29.05,64.5 ; v1(28.4,70.525) v1(29.05,70.525) v1(29.7,70.525) ; v1(31.475,69.05) v1(31.475,68.4) v1(31.475,67.75) v1(31.475,67.1) 31.475,66.75 31.35,66.625 ; 31.65,66.325 31.35,66.625 ; v1(35.875,76.375) U4.2@36.75,76.375 ; C7.2@37.997,75.05 37.998,75.048 v1(38,74.4) v1(38,74.4) ; R16.2@38.797,75 38.798,74.998 v1(38.8,74.225) v1(38.8,74.225) ; 39.075,14.85 39.275,14.85 39.875,14.25 40.325,14.25 ; U10.2@42.58,61.275 42.58,60.175 C39.1@42.78,59.975 ; v1(43.359,69.506) 43.609,69.756 U8.3@44.359,69.756 ; R36.2@49.95,69.225 50.025,69.3 50.675,69.3 C18.2@50.7,69.275 ; C18.2@50.75,69.3 v1(51.45,69.3) ; U5.8@52.75,69.15 52.75,69.7 52.65,69.8 v1(52.65,70.3) R33.2@53.275,70.3 ; C16.1@56.45,70.3 v1(56.45,71.225) ; LD3.2@61.7,70.3 61.7,69.775 v1(62,69.475) 62.275,69.75 R35.1@62.725,69.75 ; R35.1@62.75,69.75 R35.1@62.8,69.8 ; v1(27.575,66.625) 27.632,66.682 27.807,66.682 27.925,66.8 ; 27.925,66.8 28.1,66.625 v1(28.4,66.625) v1(29.05,66.625) v1(29.7,66.625) v1(30.35,66.625) v1(31,66.625) 31.35,66.625
  Top Layer w0.25: C65.1@26.4,20.9 26.325,20.975 v1(26.325,21.575) 27.082,21.575 v1@27.15,21.507 ; v1(27.15,21.575) v1@27.15,21.507 ; C66.1@27.325,20.9 27.204,21.021 27.204,21.453 v1@27.15,21.507 ; v1(27.326,57.503) 27.394,57.503 27.467,57.43 28.328,57.43 28.35,57.452 28.527,57.452 v1(28.575,57.5) ; U6.M1@32.3,63.85 32.3,63.65 32.625,63.325 v1(32.625,63.3) 32.95,63.625 U6.N1@32.95,63.85 ; v1(32.8,58.875) v1(32.8,60.2) ; v1(36.275,5.05) 36.65,5.05 U20.13@37.825,3.875 ; v1(36.55,2.625) 36.575,2.625 U20.13@37.825,3.875 ; v1(39.15,2.625) 38.847,2.928 38.772,2.928 U20.13@37.825,3.875 ; v1(39.375,5.05) 39,5.05 U20.13@37.825,3.875 ; C69.1@45.675,10.075 R55.1@47.075,10.075
  Top Layer w0.3: v1(1.525,63.85) R42.1@2.325,63.85 3.043,64.568 4.441,64.568 CN4.7@4.538,64.665 ; v1(12.355,65.985) 13.385,65.985 U9.2@13.4,66 ; 13.64,81.92 13.67,81.89 ; C47.1@20.375,39.03 20.375,38.8 20.675,38.5 v1(21.425,38.5) ; v1(22.1,64.925) C30.2@22.725,64.925 ; v1(22.1,67.225) C26.2@22.725,67.225 ; v1(22.1,68.825) C22.2@22.725,68.825 ; v1(22.1,70.075) C19.2@22.725,70.075 ; v1(22.479,14.096) 22.492,14.108 22.492,15.158 U18.2@22.504,15.171 ; C8.1@24,75.367 C8.1@24,75.375 v1(24,76) ; C9.2@25.35,75.375 v1(25.35,76.025) ; C59.1@25.675,27.75 25.7,27.75 25.805,27.855 25.805,27.88 26.23,28.305 26.23,28.325 v1@26.75,28.325 ; v1(25.825,60.8) C32.2@25.825,61.425 ; C65.1@26.334,20.9 C65.1@26.4,20.9 C66.1@27.325,20.9 27.525,20.9 27.975,21.35 U17.30@29.1,21.35 ; v1(26.6,24.9) v1@26.6,24.894 ; v1(26.765,28.335) 26.765,27.76 C60.1@26.775,27.75 27.45,27.75 27.85,27.35 U17.18@29.1,27.35 ; C63.1@27,24.2 C63.1@26.975,24.2 ; v1(27.075,60.8) C33.2@27.075,61.425 ; v1(27.326,57.503) 27.2,57.629 v1(27.2,59.45) 27.232,59.482 27.232,59.807 27.593,60.168 27.918,60.168 v1(27.95,60.2) ; C10.2@27.65,75.375 v1(27.65,76) ; C41.2@27.875,59.275 28.825,59.275 X1.4@29,59.45 ; v1@28,60.2 28.28,60.48 28.275,60.485 v1(28.275,61.325) 28.275,62.865 28.28,62.87 v1(28.075,63.075) ; v1@28.5,57.5 v1(28.575,57.5) v1(30.175,57.5) v1(31.85,57.5) 32.425,57.5 v1(32.8,57.875) v1@32.8,58.85 ; v1(28.55,7) U19.2@28.55,7.625 ; U17.32@29.1,20.35 29.8,20.35 29.8,20.325 v1(30.325,19.8) ; C11.2@29.45,75.375 v1(29.45,76) ; v1(29.975,62.85) 30,62.825 v1(30,61.425) ; C43.1@30.025,45.375 30.1,45.45 U15.2@31.2,45.45 ; v1(30.275,6.525) C70.1@30.275,7.375 C70.1@30.275,7.525 ; v1(30.312,15.812) C67.1@30.312,16.512 ; X1.2@30.35,58.4 30.5,58.55 C40.2@31.5,58.55 ; R14.2@30.425,75.375 v1(30.425,76) ; C34.2@30.625,61.425 v1(30,61.425) ; C12.1@31.375,75.375 v1(31.375,76) ; T1.2@31.638,4.563 v1(31.638,5.663) 32.443,5.663 32.638,5.858 R57.1@32.638,5.912 ; v1(31.875,60.8) 32.375,61.3 C35.2@32.375,61.425 ; v1@32.77,58.88 32.775,58.875 v1(32.8,58.875) ; v1(32.8,60.2) v1(31.275,60.2) 30.638,60.2 30,60.838 v1(30,61.425) ; v1(34.175,60.8) C36.2@34.175,61.425 ; v1(34.85,33.05) 34.85,34.7 34.175,35.375 v1(34.175,37.05) ; C51.1@34.875,37.05 v1(34.175,37.05) ; v1(35.425,60.8) C37.2@35.425,61.425 ; X2.2@35.725,37.394 35.95,37.169 35.977,37.169 X2.2@35.827,37.019 ; X2.2@35.981,37.169 36.005,37.193 36.005,37.818 36.301,38.114 36.326,38.114 36.431,38.219 C48.1@36.431,38.244 ; C48.1@36.427,38.244 36.427,38.838 36.4,38.865 ; R41.2@36.675,64.45 v1(37.3,64.45) ; C25.2@36.675,67.35 v1(37.275,67.35) ; C23.2@36.675,68.6 v1(37.3,68.6) ; C20.2@36.675,69.85 v1(37.3,69.85) ; U14.2@37.25,51.675 v1@37.25,52.217 ; X2.4@37.331,36.119 37.45,36 v1(38.45,36) ; 38.25,16.9 U17.47@38.25,18.2 ; R38.2@38.35,66.7 v1(38.35,67.325) ; v1(38.451,33.449) 38.45,33.451 v1(38.45,36) ; C21.1@40,69.025 v1(41.225,69.025) ; C49.1@40.39,37.95 40.39,38.66 40.375,38.675 ; U17.63@40.9,27.35 42.444,27.35 v1@42.684,27.591 ; C50.1@41.19,37.95 41.19,38.64 41.225,38.675 ; R59.2@41.225,4.75 41.225,4.845 41.33,4.95 41.65,4.95 v1(42,5.3) ; v1(42.35,32.775) 42.9,33.325 v1(42.9,36.35) 42.9,38.365 v1(42.59,38.675) 41.225,38.675 ; v1(42.475,0.698) 42.516,0.698 42.664,0.55 45.845,0.55 v1(46.185,0.89) ; C57.1@44.175,27 C58.1@45.1,27 v1(45.875,27) ; C56.1@44.393,29.01 v1(45.015,29.01) ; R54.1@44.825,25.65 v1(45.175,25.65) ; Q1.2@47.975,46.2 48.164,46.2 48.514,46.55 v1(48.514,47.31) ; v1(49.55,67.75) C24.1@50.3,67.75 ; R51.1@49.675,45.2 v1(49.675,45.9) ; R37.1@50.3,66.75 C24.1@50.3,67.75 ; C24.1@50.3,67.8 C24.1@50.3,67.75 ; v1@53.562,64.812 54.238,64.812 C29.1@54.25,64.8 ; LD4.3@57.425,80.05 v1(58.52,80.05) ; LD1.3@62.47,80.04 v1(63.565,80.04) ; v1@26.6,24.894 26.594,24.9 v1(25.65,24.9) 25.688,24.862 25.688,24.587 25.945,24.33 25.945,24.305 26.05,24.2 C62.1@26.075,24.2 C63.1@26.975,24.2 ; v1@26.6,24.894 26.87,24.624 26.87,24.305 C63.1@26.975,24.2 ; v1(34.175,37.05) 34.175,37.675 35.365,38.865 36.4,38.865 ; 36.4,38.865 37.86,38.865 v1(38.451,38.274) ; v1(38.45,36) 38.45,38.273 v1(38.451,38.274) ; v1(38.451,38.274) 38.852,38.675 40.375,38.675 ; 40.375,38.675 v1(40.8,38.675) 41.225,38.675
  Top Layer w0.5: v1(2.425,65.925) CN4.5@4.528,65.925
  Top Layer w0.6: v1@0.777,48.6 v1@0.777,69.425 ; v1@2.22,2.777 cw(c2.22,4.22) 0.777,4.22 0.773,4.224 v1(0.773,5.625) v1(0.773,8.95) v1(0.773,10.45) v1(0.773,13.725) v1(0.773,15.225) v1(0.773,18.5) v1(0.773,20) v1(0.773,23.35) v1(0.773,24.85) v1(0.773,28.175) v1(0.773,29.675) v1(0.773,32.775) v1(0.773,34.275) v1(0.773,37.55) v1(0.773,39.05) v1(0.773,42.325) v1(0.773,43.825) v1(0.773,47.1) v1(0.773,48.6) v1(0.773,51.925) v1(0.773,53.425) v1(0.773,56.7) v1(0.773,58.2) v1(0.773,61.5) v1(0.773,63) v1(0.773,66.275) v1(0.773,67.775) 0.773,69.421 v1@0.777,69.425 ; v1(2.225,2.802) v1(6.9,2.802) v1(8.575,2.802) v1(10.075,2.802) 11.698,2.802 v1(13.8,0.7) v1@16.948,0.7 ; v1(16.95,0.698) v1(28.075,0.698) v1(32.875,0.698) v1(37.65,0.698) v1(42.475,0.698) ; v1(46.185,0.89) v1(47.09,1.795) 47.995,2.7 67.655,2.7 ccw(c67.655,4.34) v1@69.295,4.34 ; v1(67.35,81.796) v1(64.075,81.796) v1(62.575,81.796) v1(59.225,81.796) v1(57.725,81.796) v1(54.4,81.796) v1(52.9,81.796) 52.898,81.798 v1(41.875,81.798) 41.867,81.79 v1(2.252,81.79) ccw(c2.252,80.315) 0.777,80.315 v1(0.777,78.925) v1@0.777,69.425 ; v1@67.502,81.79 cw(c67.502,79.997) 69.295,79.997 v1@69.295,4.34 ; v1(69.296,10.425) v1(69.296,8.925) v1(69.296,5.6) 69.296,4.341 v1@69.295,4.34
  Signal Layer 1 w0.3: 13.64,81.92 13.67,81.89 ; v1@42.72,0.7 42.82,0.7 42.97,0.55 45.845,0.55 v1(46.185,0.89)
  Signal Layer 1 w0.6: 13.67,81.8 13.67,81.79 ; v1@42.72,0.7 13.79,0.7 v1(12.85,1.64) 11.713,2.777 2.22,2.777 cw(c2.22,4.22) 0.777,4.22 v1(0.777,78.925) 0.777,80.315 cw(c2.252,80.315) v1(2.252,81.79) 13.67,81.79 ; v1(46.185,0.89) v1(47.09,1.795) 47.995,2.7 67.655,2.7 ccw(c67.655,4.34) 69.295,4.34 69.295,32.75 69.295,79.997 ccw(c67.502,79.997) 67.502,81.79 13.67,81.79
  Signal Layer 2 w0.3: v1@27.251,57.501 v1@27.251,57.503 ; v1@28.5,57.5 v1(28.575,57.5) v1(30.175,57.5) ; v1@30.475,81.79 30.475,81.4 30.825,81.05 ; v1(42.475,0.698) 42.516,0.698 42.664,0.55 45.845,0.55 v1(46.185,0.89)
  Signal Layer 2 w0.6: v1(0.773,43.825) v1(0.773,42.325) v1(0.773,39.05) v1(0.773,37.55) v1(0.773,34.275) v1(0.773,32.775) v1(0.773,29.675) v1(0.773,28.175) v1(0.773,24.85) v1(0.773,23.35) v1(0.773,20) v1(0.773,18.5) v1(0.773,15.225) v1(0.773,13.725) v1(0.773,10.45) v1(0.773,8.95) v1(0.773,5.625) 0.773,4.224 0.777,4.22 ccw(c2.22,4.22) v1@2.22,2.777 ; v1@0.777,43.825 v1(0.777,78.925) 0.777,80.315 cw(c2.252,80.315) v1(2.252,81.79) 13.67,81.79 30.475,81.79 67.502,81.79 cw(c67.502,79.997) 69.295,79.997 69.295,35.9 69.295,4.34 cw(c67.655,4.34) 67.655,2.7 47.995,2.7 v1(47.09,1.795) v1(46.185,0.89) ; v1(2.225,2.802) v1(6.9,2.802) v1(8.575,2.802) v1(10.075,2.802) 11.698,2.802 v1(13.8,0.7) v1(26.425,0.7) v1@42.473,0.7
  Bottom Layer w0.2: U22.B2@47.825,62.075 U22.B1@47.825,62.575 47.844,62.594 47.844,62.689 48.7,63.545 49.105,63.545 49.375,63.275 49.375,62.2 v1(49,61.825)
  Bottom Layer w0.3: 13.64,81.92 13.67,81.89 ; v1(27.85,32.11) 28.47,32.11 28.545,32.185 28.57,32.185 28.675,32.29 C72.1@28.675,32.315 ; v1(30.075,36.225) 30.075,35.375 SB12.1@30.375,35.075 ; C73.2@32.683,64.033 32.683,63.358 v1(32.625,63.3) 33.602,63.3 R31.2@33.761,63.458 ; v1@42.473,0.7 42.514,0.7 42.664,0.55 45.845,0.55 v1(46.185,0.89)
  Bottom Layer w0.6: v1(0.775,40.7) v1(0.775,35.925) v1(0.775,31.325) v1(0.775,26.5) v1(0.775,21.65) v1(0.775,16.875) v1(0.775,12.1) v1(0.775,7.275) 0.775,4.222 0.777,4.22 ccw(c2.22,4.22) v1@2.22,2.777 ; v1@0.777,40.7 v1(0.777,78.925) 0.777,80.315 cw(c2.252,80.315) v1(2.252,81.79) 13.67,81.79 67.502,81.79 cw(c67.502,79.997) 69.295,79.997 v1@69.295,42.3 ; v1(2.225,2.802) v1(6.9,2.802) v1(8.575,2.802) v1(10.075,2.802) 11.698,2.802 v1(13.8,0.7) v1(26.425,0.7) v1@42.473,0.7 ; v1(46.185,0.89) v1(47.09,1.795) 47.995,2.7 67.655,2.7 ccw(c67.655,4.34) 69.295,4.34 69.296,4.341 v1(69.296,5.6) v1(69.296,8.925) v1(69.296,10.425) v1(69.296,13.7) v1(69.296,15.2) v1(69.296,18.475) v1(69.296,19.975) v1(69.296,23.325) v1(69.296,24.825) v1(69.296,28.15) v1(69.296,29.65) v1(69.296,32.75) v1(69.296,34.25) v1(69.296,37.525) v1(69.296,39.025) v1(69.296,42.3)
  other v1: 15.45,0.698 18.175,0.709 19.825,0.707 21.475,0.706 23.125,0.704 24.775,0.702 29.725,0.696 31.225,0.696 34.525,0.696 36.025,0.696 39.3,0.696 40.8,0.696 48,2.7 49.65,2.698 51.15,2.698 52.825,2.698 54.475,2.696 55.975,2.696 57.5,2.698 59.15,2.696 60.65,2.696 62.275,2.698 63.925,2.696 65.425,2.696 67.075,2.698 3.75,2.804 5.25,2.804 11.725,2.8 68.75,3.1 1.2,3.2 28.175,3.425 35.625,3.875 69.296,4.1 0.773,4.125 35.5,6.55 69.298,7.25 34.798,8.687 50.35,8.725 44.7,10.15 17.6,11.875 69.298,12.075 30.25,12.125 25.725,12.2 27.35,12.875 30.375,13.9 25.85,14.35 20.725,14.375 47.7,14.575 37.55,14.925 49.475,14.95 44.475,15.075 53.7,16.525 17.65,16.725 69.298,16.85 49.025,18.275 40.525,19.375 45.55,19.5 53.875,20.1 19.325,20.475 23.1,21.291 36.5,21.375 69.298,21.625 47.55,22.125 43.425,22.75 39.225,24.675 21.826,26.026 69.298,26.475 31,26.875 36.8,26.975 42.675,27.6 49.05,27.625 22.9,28.4 69.298,31.3 33.25,32.15 39.25,32.175 43.525,32.55 47.875,32.625 57.225,33.725 69.298,35.9 49.375,36.9 45.4,36.975 52.349,38.583 69.298,40.675 8.675,40.725 30.025,41.625 51.55,42.85 45.825,43.75 69.296,43.8 31.88,44.435 33.13,44.435 11.25,44.55 30.03,44.685 8.95,44.825 52.25,44.9 32.5,45.45 69.298,45.45 0.775,45.475 36.11,45.695 12.25,45.8 34.985,46.195 17.45,46.5 31.88,46.485 33.13,46.485 45.575,46.55 14.35,47.025 69.296,47.075 38.08,47.11 51.825,47.2 18.3,47.225 19.275,47.325 17.075,47.35 35.725,47.45 32.23,47.71 9,47.95 22.575,48.375 25.2,48.475 69.296,48.575 12.95,49.55 69.298,50.225 0.775,50.25 51.825,50.625 55.475,50.825 7.875,51.15 61.15,51.8 69.296,51.9 37.255,52.222 3.325,52.775 13.375,52.975 8.65,53.05 66.8,53.2 63.45,53.225 69.296,53.4 6.3,54.075 61.544,54.178 69.298,55.05 0.775,55.075 33.825,55.5 4.025,55.575 8.675,55.725 50.125,56.175 69.296,56.675 64.084,56.998 69.296,58.175 3.125,58.2 34.3,58.2 50.675,58.4 24.025,58.475 11,59 42.475,59.075 8,59.4 38.25,59.75 69.298,59.825 0.775,59.85 23.825,59.95 45.3,60.3 18.575,60.55 2.1,60.65 63.983,60.833 69.296,61.475 69.296,62.975 38.25,63 44.375,64 20.85,64.25 63.957,64.389 69.298,64.625 0.775,64.65 53.55,64.825 47.65,65.15 46.15,65.775 69.296,66.25 69.296,67.75 63.373,67.869 46.125,67.925 53.5,68.25 10.575,68.55 69.298,69.4 0.775,69.425 2.85,69.95 41.25,70.8 69.296,70.925 0.773,70.95 39.45,70.95 61.671,71.2 36.25,71.45 9.875,71.525 69.296,72.425 0.773,72.45 38.1,72.5 41.225,72.5 16.575,72.675 14.15,73 35,73.525 1.7,73.7 69.298,74.075 0.775,74.1 18.65,74.875 34.875,74.975 69.298,75.75 0.775,75.775 63.55,75.9 32.65,76.45 29.375,76.9 69.298,77.25 0.775,77.275 8.575,78.25 11.2,78.25 69.3,78.9 22.85,79.15 40.85,79.6 64.775,80 4.5,80.25 69.3,80.4 0.8,80.7 68.7,81.3 1.275,81.45 3.65,81.8 5.3,81.798 6.8,81.798 8.475,81.798 10.125,81.796 11.625,81.796 13.15,81.798 14.8,81.796 16.3,81.796 17.925,81.798 19.575,81.796 21.075,81.796 22.725,81.798 24.375,81.796 25.875,81.796 27.5,81.798 29.15,81.796 30.65,81.796 32.325,81.798 33.975,81.796 35.475,81.796 37.1,81.798 38.625,81.794 40.25,81.796 43.5,81.8 45.125,81.802 46.75,81.804 48.375,81.806 50,81.807 51.625,81.809 56.075,81.798 60.925,81.798 65.7,81.798
GNDDetect: CN4.11 R42.2 | length 2.9
  Top Layer w0.3: R42.2@2.325,62.95 2.325,62.375 2.575,62.125 CN4.11@4.538,62.125
HiZ_DBG_IF_EN: JP1.2 R28.2 U2.9 | length 16
  Top Layer w0.12: JP1.2@6.63,80.05 4.625,78.045 4.625,71.9 5.175,71.35 6.775,71.35 6.95,71.525 R28.2@6.95,71.975 ; R28.2@6.965,72.11 7.145,72.29 7.407,72.29 7.617,72.5 10,72.5 10.125,72.625 U2.9@10.125,73.175
IOREF: CN6.2 CN7.12 SB9.2 SB11.2 | length 13.4
  Top Layer w0.5: CN7.12@5.79,38.06 CN6.2@10.87,38.06 16.035,38.06 v1(16.375,38.4)
  Bottom Layer w0.5: SB9.2@15.325,40.025 SB11.2@15.325,38.4 v1(16.375,38.4)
